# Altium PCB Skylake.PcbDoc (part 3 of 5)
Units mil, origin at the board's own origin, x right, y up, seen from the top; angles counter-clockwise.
Board outline 4000 x 4000 mil, 8 copper layers (TOP LAYER, GND1#2, SIG1#3, SIG2#4, GND2#5, SIG3#6, GND3#7, BOTTOM LAYER), stack 132.6 mil thick; 343 components, 142 nets, 972 pads, 752 vias.
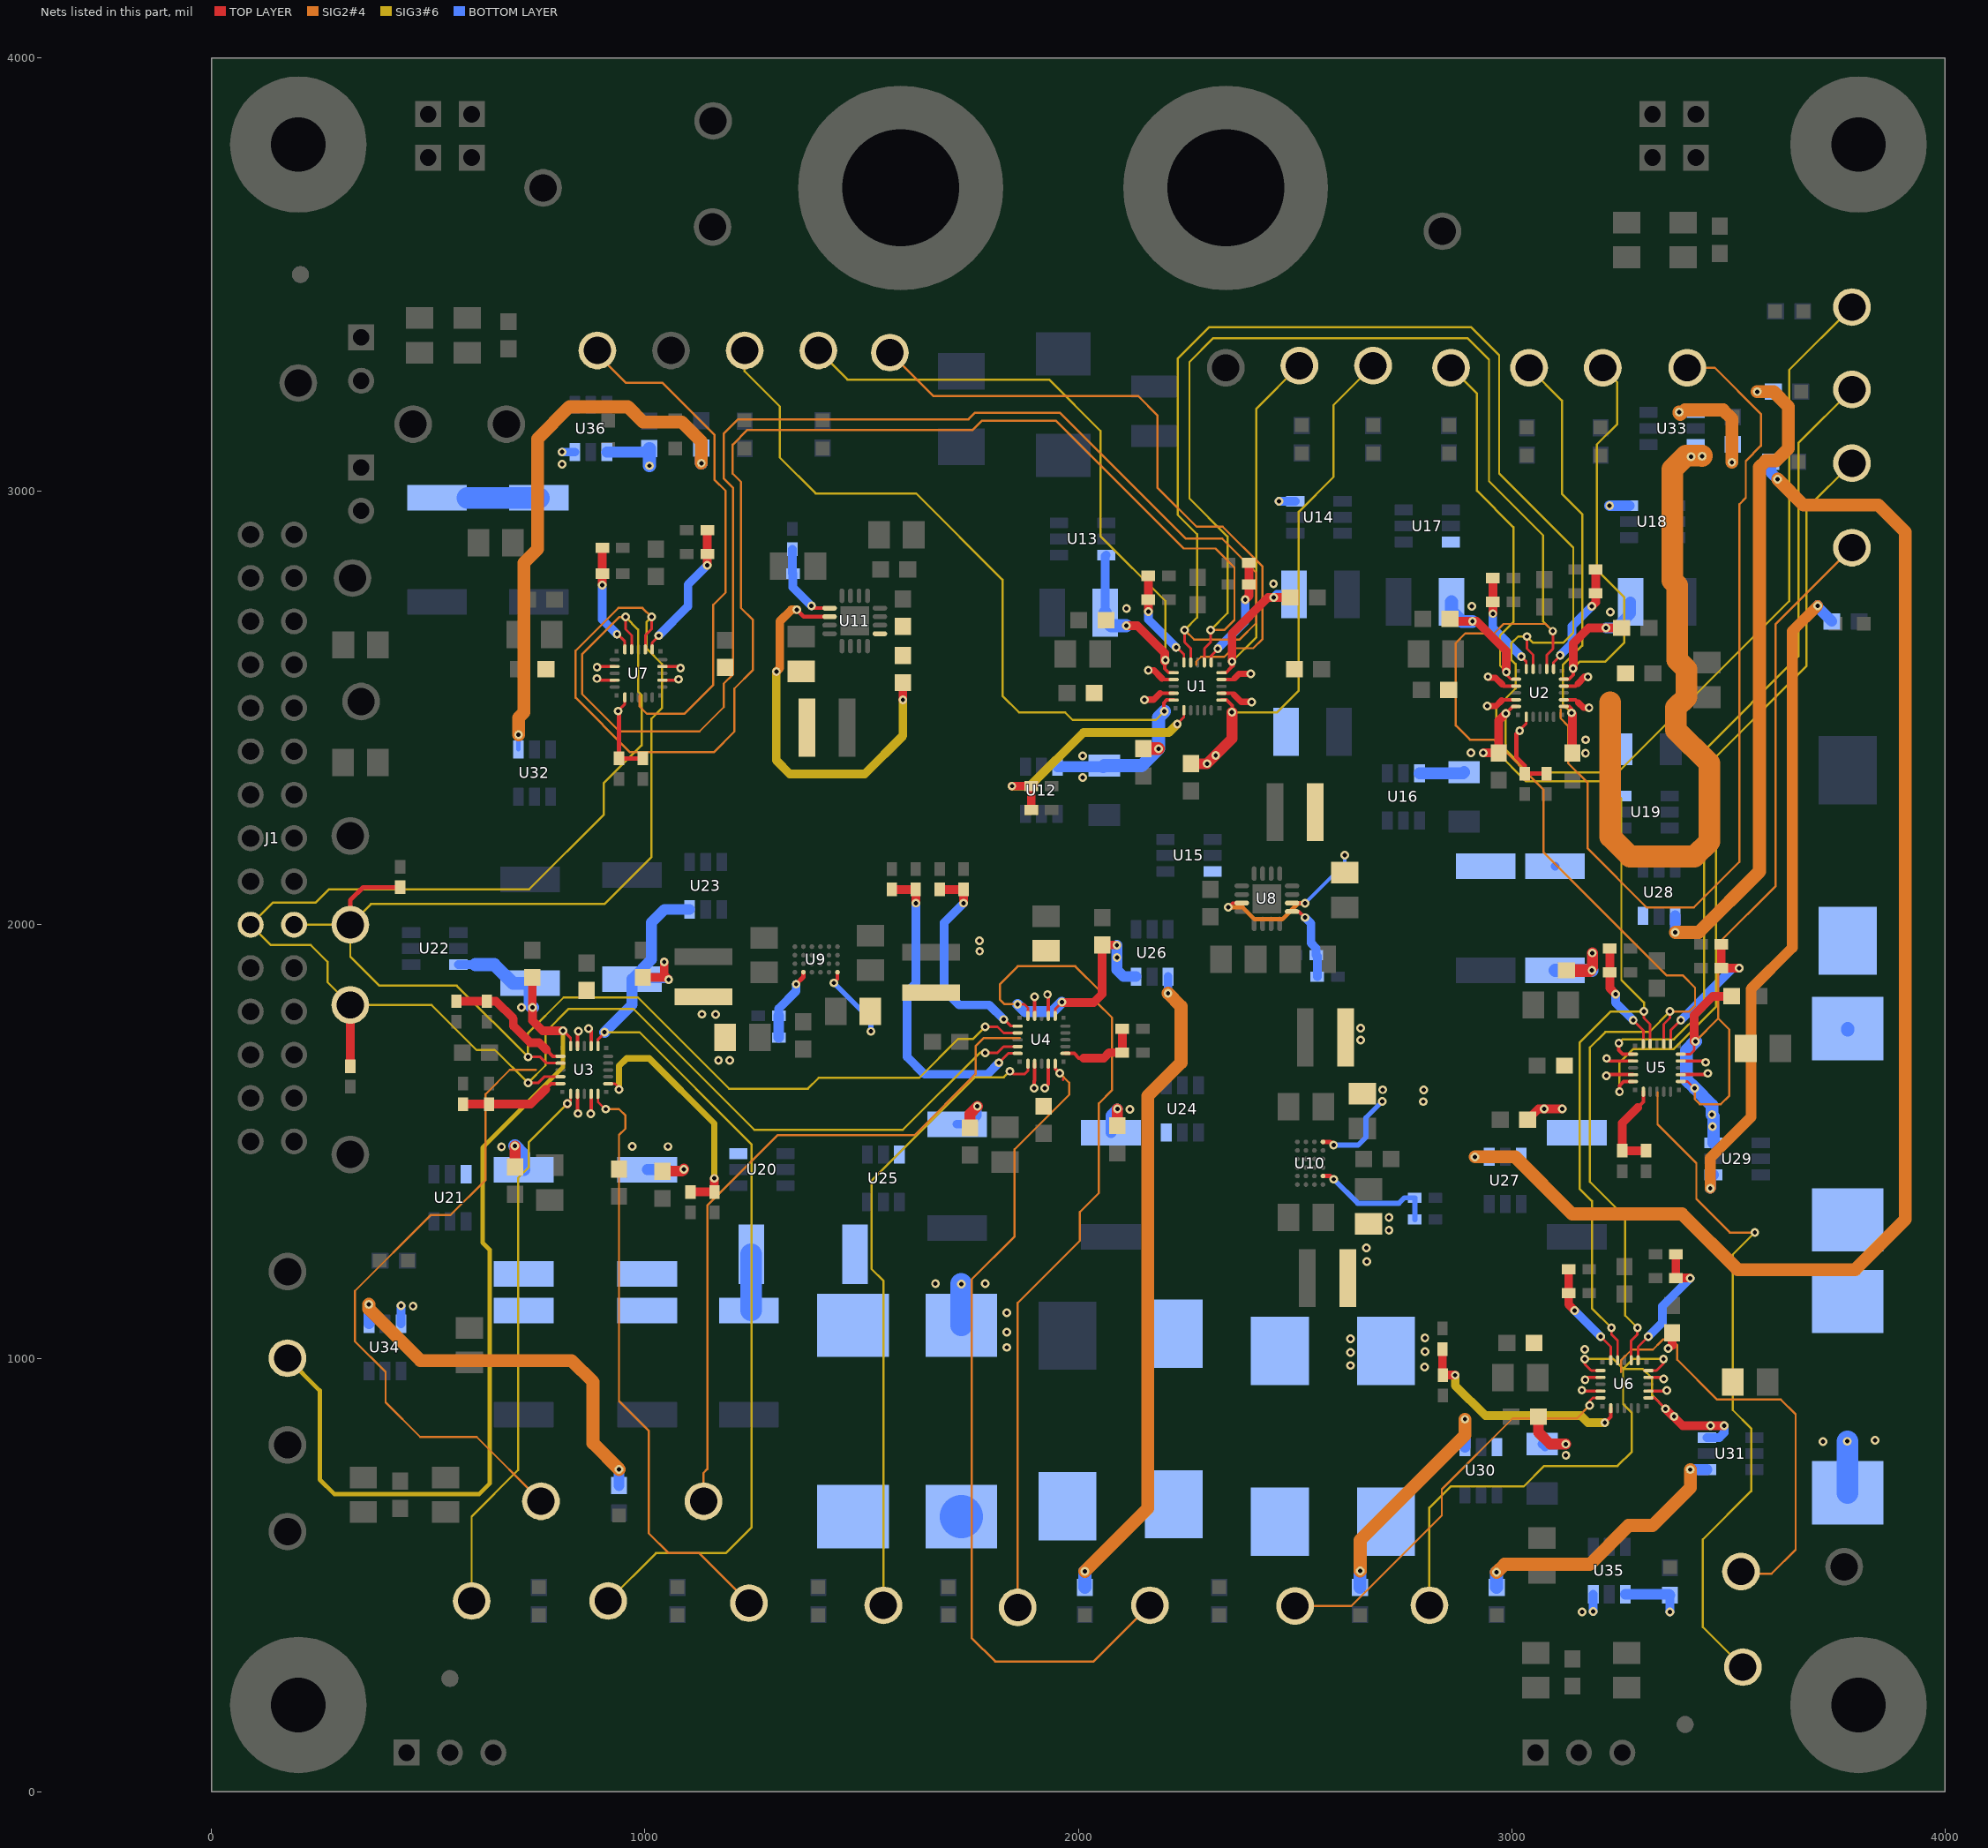
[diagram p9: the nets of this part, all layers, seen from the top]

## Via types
v1: diameter 20, hole 10, TOP LAYER to BOTTOM LAYER, 742 vias
v2: diameter 19.68, hole 7.87, TOP LAYER to BOTTOM LAYER, 10 vias

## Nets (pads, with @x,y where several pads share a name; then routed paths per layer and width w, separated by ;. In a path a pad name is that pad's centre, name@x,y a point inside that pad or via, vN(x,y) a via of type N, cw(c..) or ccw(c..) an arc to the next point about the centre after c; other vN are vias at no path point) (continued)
NetR17_2: R17.2 U26.1 | length 1513.1
  SIG2#4 w30: v1(2015.14,508.53) 2160,653.39 2160,1605 2236.74,1681.74 2236.74,1812.15 v1(2206.84,1842.05)
  BOTTOM LAYER w20: v1(2206.84,1842.05) 2207,1842.21 U26.1@2207,1880.5
  BOTTOM LAYER w30: R17.2@2015,471.5 v1@2015,508.39
NetR18_2: R18.2 U27.1 | length 3159.7
  SIG2#4 w30: v1(2915.19,1464.5) 3007.52,1464.5 3139.32,1332.7 3393.16,1332.7 3521.68,1204.18 3792.25,1204.18 3908.14,1320.07 3908.14,2906.31 3846.16,2968.29 3673.18,2968.29 v1(3613.56,3027.91)
  BOTTOM LAYER w25: v1(2915.19,1464.5) U27.1@2948,1464.5 ; R18.2@3597.27,3068.13 3597.27,3044.2 v1(3613.56,3027.91)
NetR19_2: R19.2 U28.1 | length 1528.1
  SIG2#4 w30: v1(3377.38,1982.27) 3430.89,1982.27 3571.55,2122.93 3571.55,3056.11 3585.93,3070.49 3609.85,3070.49 3638.31,3098.95 3638.31,3195.65 3604.11,3229.85 v1(3566.55,3229.85)
  BOTTOM LAYER w10: v1(3566.55,3229.85) 3566.7,3230 R19.2@3603.5,3230
  BOTTOM LAYER w25: U28.1@3377,2020.5 3377,1982.65 v1(3377.38,1982.27)
NetR20_2: R20.2 U29.1 | length 1530.3
  SIG2#4 w25: v1(3458,1392) 3458,1462.29 3552,1556.29 3552,1851.89 3647.48,1947.37 3647.48,2677.48 v1(3706,2736)
  BOTTOM LAYER w25: v1(3458,1392) 3458,1415.5 U29.1@3465.5,1423 ; v1(3706,2736) 3706,2732.5 R20.2@3738.5,2700
NetR21_2: R21.2 U30.1 | length 551.6
  SIG2#4 w30: v1(2650.14,509.51) 2650.14,580.37 2892.11,822.34 v1(2892.11,859.17)
  BOTTOM LAYER w25: U30.1@2892,795.19 v1@2892,859.06
  BOTTOM LAYER w30: R21.2@2650,471.5 v1@2650,509.37
NetR22_2: R22.2 U31.1 | length 642.6
  SIG2#4 w30: v1(2965,506.26) 2983.22,524.48 3179.76,524.48 3269.28,614 3324.46,614 3412,701.54 v1(3412,743)
  BOTTOM LAYER w25: v1(3412,743) U31.1@3450.5,743
  BOTTOM LAYER w30: R22.2@2965,471.5 v1(2965,506.26)
NetR23_2: R23.2 U32.1 | length 1271.5
  SIG2#4 w30: v1(708.2,2438.34) 708.2,2443.27 708.32,2443.39 708.32,2477.9 720.38,2489.96 720.38,2835.06 752.05,2866.73 752.05,3121.18 825.87,3195 960.38,3195 995.38,3160 1085,3160 1130,3115 v1(1130,3065)
  BOTTOM LAYER w10: U32.1@708,2404.5 708,2443.07 708.2,2443.27 v1(708.2,2438.34)
  BOTTOM LAYER w30: v1(1130,3065) R23.2@1130,3100
NetR24_2: R24.2 U33.1 | length 320.7
  SIG2#4 w30: v1(3386,3183) 3386,3180 3389,3177 3399.59,3187.59 3487.99,3187.59 3508,3167.58 v1(3508,3067)
  BOTTOM LAYER w20: v1(3386,3183) 3423.5,3183 U33.1@3424.5,3182 ; v1(3508,3067) 3508,3106.5 R24.2@3510,3108.5
NetR25_2: R25.2 U34.1 | length 906
  SIG2#4 w30: v1(362.91,1124.29) 362.91,1113.68 482.11,994.49 830.65,994.49 880,945.14 880,803.67 v1(940.14,743.53)
  BOTTOM LAYER w10: v1(362.91,1124.29) v1@363,1124.2 ; v1@940,743.39 v1(940.14,743.53)
  BOTTOM LAYER w25: U34.1@363,1079.5 v1@363,1124.2 ; R25.2@940,706.5 v1@940,743.39
NetR26_2: R26.2 U35.1 | length 142.3
  BOTTOM LAYER w20: v1(3365,415) R26.2@3365,453.5
  BOTTOM LAYER w25: U35.1@3262,455.5 3363,455.5 R26.2@3365,453.5
NetR27_2: R27.2 U36.1 | length 140.8
  BOTTOM LAYER w25: U36.1@912,3090.5 1002,3090.5 R27.2@1010,3098.5
  BOTTOM LAYER w30: v1(1010,3059) R27.2@1010,3098.5
NetR29_1: R29.1 R32.2 U1.6 | length 578.8
  TOP LAYER w6: v1(2228.21,2462.92) 2228.21,2464.16 2243.5,2479.45 U1.6@2243.5,2494.88
  TOP LAYER w20: v1(1846.68,2319.94) 1846.74,2320 R29.1@1891.38,2320 R32.2@1891.38,2265
  SIG3#6 w20: v1(1846.68,2319.94) 1887.94,2319.94 2011.58,2443.58 2208.87,2443.58 v1(2228.21,2462.92)
NetR30_1: R30.1 R33.2 U1.16 | length 266
  TOP LAYER w6: U1.16@2306.5,2605.12 2306.5,2620.55 2321.79,2635.84 v1(2321.79,2637.08)
  TOP LAYER w20: v1(2385,2750) 2393.62,2758.62 R30.1@2393.62,2785 R33.2@2393.62,2835
  BOTTOM LAYER w20: v1(2321.79,2637.08) 2385,2700.29 v1(2385,2750)
NetR31_1: R31.1 R34.2 U1.20 | length 236.8
  TOP LAYER w6: v1(2225.38,2640.26) 2225.38,2641.83 2243.5,2623.71 U1.20@2243.5,2605.12
  TOP LAYER w20: v1@2161.38,2722.82 R31.1@2161.38,2750 R34.2@2161.38,2805
  BOTTOM LAYER w20: v1(2161.56,2722.64) 2161.56,2704.08 v1(2225.38,2640.26)
NetR39_1: R39.1 R42.2 U2.6 | length 198.6
  TOP LAYER w6: v1(3018.21,2447.92) 3018.21,2449.16 3033.5,2464.45 U2.6@3033.5,2479.88
  TOP LAYER w10: v1(3018.21,2447.92) 3010.85,2440.56 3010.85,2386.06 3030,2366.91 R39.1@3030,2348.62 R42.2@3080,2348.62
NetR40_1: R40.1 R43.2 U2.16 | length 270.1
  TOP LAYER w6: U2.16@3096.5,2590.12 3096.5,2605.55 3111.79,2620.84 v1(3111.79,2622.08)
  TOP LAYER w20: v1(3185,2735) 3193.62,2743.62 R40.1@3193.62,2765 R43.2@3193.62,2820
  BOTTOM LAYER w20: v1(3111.79,2622.08) 3139.07,2649.36 3139.07,2689.07 v1(3185,2735)
NetR41_1: R41.1 R44.2 U2.20 | length 241.9
  TOP LAYER w6: v1(3022.2,2618.44) 3033.5,2607.14 U2.20@3033.5,2590.12
  TOP LAYER w20: v1(2956.31,2717.85) 2956.38,2717.92 R41.1@2956.38,2745 R44.2@2956.38,2800
  BOTTOM LAYER w20: v1(2956.31,2717.85) 2956.31,2684.33 v1(3022.2,2618.44)
NetR50_1: R50.1 R53.2 U3.6 | length 602.9
  TOP LAYER w6: U3.6@915.12,1633.5 930.55,1633.5 v1@944.05,1620 ; v1(940,1620) v1@944.05,1620 ; v1@944.05,1620 945.29,1620 947.08,1618.21 945.84,1618.21 v1@944.05,1620
  TOP LAYER w20: R50.1@1105,1383.62 R53.2@1160,1383.62 v1(1160,1415)
  SIG3#6 w15: v1(940,1620) 940,1674.31 957.59,1691.9 1009.62,1691.9 1160,1541.52 v1(1160,1415)
NetR51_1: R51.1 R54.2 U3.16 | length 302.4
  TOP LAYER w8: 772.6,1711.54 787.64,1696.5 U3.16@804.88,1696.5
  TOP LAYER w20: R54.2@565,1823.62 R51.1@635,1823.62 656.26,1823.62 696.31,1783.57 696.31,1766.78 734.97,1728.12 756.02,1728.12 772.6,1711.54
NetR52_1: R52.1 R55.2 U3.20 | length 244.4
  TOP LAYER w8: 770.7,1620.6 783.6,1633.5 U3.20@804.88,1633.5
  TOP LAYER w20: R55.2@580,1586.38 R52.1@640,1586.38 736.48,1586.38 770.7,1620.6
NetR56_2: R56.2 R57.1
NetR58_2: R58.2 R59.1
NetR62_1: R62.1 R65.2 U4.6 | length 195.8
  TOP LAYER w8: U4.6@1970.12,1703.19 1990.45,1703.19 2001.06,1692.58 2012.18,1692.58
  TOP LAYER w20: 2012.18,1692.58 2058.89,1692.58 2071.31,1705 R62.1@2101.38,1705 R65.2@2101.38,1760
NetR63_1: R63.1 R66.2 U4.16 | length 509.9
  TOP LAYER w6: v1(1827.92,1781.48) 1829.16,1781.48 1844.45,1766.18 U4.16@1859.88,1766.18
  TOP LAYER w20: R63.1@1680,2081.38 R66.2@1735,2081.38 v1(1735,2050)
  BOTTOM LAYER w20: v1(1735,2050) 1690,2005 1690,1849.49 1724.49,1815 1794.4,1815 v1(1827.92,1781.48)
NetR64_1: R64.1 R67.2 U4.20 | length 741.1
  TOP LAYER w6: v1(1816.47,1681.58) 1838.08,1703.19 U4.20@1859.88,1703.19
  TOP LAYER w20: R67.2@1570,2081.38 R64.1@1625,2081.38 v1(1625,2050)
  BOTTOM LAYER w20: v1(1625,2050) 1625,1865 1605,1845 1605,1695 1645,1655 1789.89,1655 v1(1816.47,1681.58)
NetR70_2: R70.2 R71.1 | length 0
NetR71_2: R71.2 R72.1
NetR72_2: R72.2 R73.1 | length 129.9
  BOTTOM LAYER w50: R73.1@1244.92,1110.08 R72.2@1244.92,1240
NetR75_1: R75.1 R78.2 U5.6 | length 211.4
  TOP LAYER w8: 3290.78,1578.39 3303.5,1591.11 U5.6@3303.5,1614.88
  TOP LAYER w20: 3290.78,1578.39 3255,1542.61 R75.1@3255,1478.62 R78.2@3310,1478.62
NetR76_1: R76.1 R79.2 U5.16 | length 345.7
  TOP LAYER w6: U5.16@3366.5,1725.12 3366.5,1756.5 v1(3390,1780)
  TOP LAYER w20: R79.2@3483.62,1955 R76.1@3483.62,1900 v1(3525,1900)
  BOTTOM LAYER w20: v1(3390,1780) 3510,1900 v1(3525,1900)
NetR77_1: R77.1 R80.2 U5.20 | length 251.8
  TOP LAYER w6: v1(3280,1780) 3303.5,1756.5 U5.20@3303.5,1725.12
  TOP LAYER w20: R80.2@3226.38,1945 R77.1@3226.38,1890 3226.38,1853.62 v1(3240,1840)
  BOTTOM LAYER w20: v1(3240,1840) 3240,1820 v1(3280,1780)
NetR82_2: R82.2 R83.1 | length 0
NetR84_2: R84.2 R85.1
NetR85_2: R85.2 R86.1 | length 3.5
  BOTTOM LAYER w30: R85.2@3775,1756.94 R85.2@3775,1760.47
NetR87_1: R87.1 R90.2 U6.6 | length 533.2
  TOP LAYER w8: v1(3214.73,851.2) 3228.5,864.97 U6.6@3228.5,884.88
  TOP LAYER w20: R90.2@2840,1021.38 2840,962.07 R87.1@2840.9,961.17 2869.26,961.17 v1(2869.53,960.9)
  SIG3#6 w20: v1(2869.53,960.9) 2869.53,937.2 2939.21,867.52 3159.12,867.52 3175.44,851.2 v1(3214.73,851.2)
NetR88_1: R88.1 R91.2 U6.16 | length 326.3
  TOP LAYER w6: U6.16@3291.5,995.12 3291.5,1026.5 v1(3315,1050)
  TOP LAYER w20: R91.2@3378.62,1240 R88.1@3378.62,1185 v1@3410.93,1185
  BOTTOM LAYER w20: v1(3315,1050) 3347.39,1082.39 3347.39,1120.28 v1(3411.52,1184.41)
NetR89_1: R89.1 R92.2 U6.20 | length 250.1
  TOP LAYER w6: v1(3205,1050) 3228.5,1026.5 U6.20@3228.5,995.12
  TOP LAYER w20: R92.2@3131.38,1205 R89.1@3131.38,1150 3131.38,1123.62 v1(3145,1110)
  BOTTOM LAYER w20: v1(3145,1110) v1(3205,1050)
NetR94_2: R94.2 R95.1
NetR95_2: R95.2 R96.1
NetR96_2: R96.2 R97.1
NetR99_1: R99.1 R102.2 U7.6 | length 203.3
  TOP LAYER w6: v1@938.21,2494.16 953.5,2509.45 U7.6@953.5,2524.88
  TOP LAYER w10: v1@938.21,2494.16 940,2492.37 R99.1@940,2383.62 R102.2@995,2383.62
  other v1: 938.21,2492.92
NetR100_1: R100.1 R103.2 U7.16 | length 327.5
  TOP LAYER w6: U7.16@1016.5,2635.12 1016.5,2650.55 1031.79,2665.84 v1(1031.79,2667.08)
  TOP LAYER w20: v1(1143.5,2829.3) 1143.62,2829.42 R100.1@1143.62,2855 R103.2@1143.62,2910
  BOTTOM LAYER w20: v1(1031.79,2667.08) 1099.12,2734.41 1099.12,2784.92 v1(1143.5,2829.3)
NetR101_1: R101.1 R104.2 U7.20 | length 259.5
  TOP LAYER w6: v1(935.38,2670.26) 935.38,2671.83 953.5,2653.71 U7.20@953.5,2635.12
  TOP LAYER w20: v1(901.43,2783.39) R101.1@901.38,2810 R104.2@901.38,2870
  BOTTOM LAYER w20: v1(901.43,2783.39) 901.43,2704.21 v1(935.38,2670.26)
NetR105_2: R105.2 R106.1 | length 165
  BOTTOM LAYER w50: 590,2985.08 R105.2@755,2985.08
NetR107_2: R107.2 R108.2 U8.13 | length 184
  TOP LAYER w8: U8.13@2493.07,2030.47 2509.03,2030.47 v1(2522.85,2016.65)
  BOTTOM LAYER w20: v1(2522.85,2016.65) 2536.92,2002.58 2536.92,1957.53 2548.62,1945.83 R107.2@2548.62,1930 2551.38,1927.24 R108.2@2551.38,1880
NetR109_1: R109.1 R110.2 U9.E4 | length 174
  TOP LAYER w10: v1(1348.77,1862.82) 1365.47,1879.52 U9.E4@1365.47,1890.47
  BOTTOM LAYER w20: R110.2@1308.62,1790 1308.62,1806.65 1348.77,1846.8 v1(1348.77,1862.82)
  BOTTOM LAYER w25: R109.1@1308.62,1740 R110.2@1308.62,1790
NetR111_1: R111.1 R112.2 U10.E4 | length 293.1
  TOP LAYER w10: U10.E4@2564.37,1420.31 2581.62,1420.31 v1(2589.13,1412.8)
  BOTTOM LAYER w12: v1(2589.13,1412.8) 2644.34,1357.59 2739.8,1357.59 2752.21,1370 R111.1@2776.38,1370 R112.2@2776.38,1320
NetR113_1: R113.1 R114.2 U11.13 | length 195.7
  TOP LAYER w8: v1(1384.18,2735.97) 1389.62,2730.53 U11.13@1428.88,2730.53
  BOTTOM LAYER w20: R114.2@1340,2866.38 1340,2811.38 R113.1@1341.38,2810 1341.38,2778.77 v1(1384.18,2735.97)
NetR115_1: R115.1 R116.2 U11.5
SCL: J1.20 R1.1 SCL.1 U1.17 U2.17 U3.17 U4.17 U5.17 U6.17 U7.17 | length 11517.1
  TOP LAYER w6: v1(730,1695) 758.41,1695 772.66,1680.75 U3.17@804.88,1680.75 ; U7.17@1000.75,2635.12 1000.75,2667.34 1015,2681.59 v1(1015,2710) ; v1(1785,1764.68) 1813.41,1764.68 1827.66,1750.43 U4.17@1859.88,1750.43 ; U1.17@2290.75,2605.12 2290.75,2637.34 2305,2651.59 v1(2305,2680) ; U2.17@3080.75,2590.12 3080.75,2622.34 3095,2636.59 3095,2677.03 v1(3094.7,2677.33) ; U6.17@3275.75,995.12 3275.75,1040.75 3290,1055 v1(3290,1070) ; U5.17@3350.75,1725.12 3350.75,1770.75 3365,1785 v1(3365,1800)
  TOP LAYER w10: SCL.1@320,2000 320,2056.94 349.44,2086.38 R1.1@435,2086.38
  SIG2#4 w5: v1(1015,2710) 994.19,2730.81 938.46,2730.81 840.12,2632.47 840.12,2523.77 965.74,2398.15 1158.47,2398.15 1206.27,2445.95 1206.27,2544.8 1249.36,2587.89 1249.36,2703.01 1221.38,2730.99 1221.38,3021.62 1202.35,3040.65 1202.35,3107.72 1236.28,3141.65 1756.18,3141.65 1777.72,3163.19 1947.96,3163.19 2243.03,2868.12 2316.68,2868.12 2360.13,2824.67 2360.13,2703.11 2337.02,2680 v1(2305,2680) ; v1(3094.7,2677.33) 3078.02,2694.01 2981.05,2694.01 2959.19,2672.15 2892.89,2672.15 2870.86,2650.12 2870.86,2459.71 2903.57,2427 2958.24,2427 3073,2312.24 3073,2167.49 3357.05,1883.44 3394.14,1883.44 3422.96,1854.62 3422.96,1813.64 3409.32,1800 v1(3365,1800)
  SIG3#6 w5: J1.20@190,2000 SCL.1@320,2000 ; v1(1015,2710) 1004,2699 1004,2636.88 1038.89,2601.99 1038.89,2499.65 1015,2475.76 1015,2156.41 906.25,2047.66 367.66,2047.66 SCL.1@320,2000 ; v1(1785,1764.68) 1757.32,1737 1723,1737 1633,1647 1401,1647 1376,1622 1194,1622 983.78,1832.22 812.12,1832.22 730,1750.11 v1(730,1695) 565.54,1859.46 387,1859.46 320,1926.46 SCL.1@320,2000 ; v1(2305,2680) 2344.04,2719.04 2344.04,2895.92 2256.32,2983.64 2256.32,3298.32 2311.4,3353.4 2897.67,3353.4 2947.49,3303.58 2947.49,3023.29 3072.15,2898.63 3072.15,2699.88 v1(3094.7,2677.33) ; v1(3290,1070) 3261.52,1098.48 3261.52,1325.76 3180.11,1407.17 3180.11,1716.82 3215.94,1752.65 3317.65,1752.65 v1(3365,1800)
SDA: J1.19 R2.1 SDA.1 U1.19 U2.19 U3.19 U4.19 U5.19 U6.19 U7.19 | length 11600.7
  TOP LAYER w6: v1(730,1635) 753.16,1635 767.41,1649.25 U3.19@804.88,1649.25 ; v1(955,2710) 955,2681.88 969.25,2667.63 U7.19@969.25,2635.12 ; v1(1785,1704.69) 1813.12,1704.69 1827.37,1718.94 U4.19@1859.88,1718.94 ; v1(2245,2680) 2245,2651.88 2259.25,2637.63 U1.19@2259.25,2605.12 ; v1(3035,2665) 3035,2636.88 3049.25,2622.63 U2.19@3049.25,2590.12 ; v1(3230,1070) 3230,1055 3244.25,1040.75 U6.19@3244.25,995.12 ; v1(3305,1800) 3305,1785 3319.25,1770.75 U5.19@3319.25,1725.12
  TOP LAYER w20: R2.1@320,1673.62 SDA.1@320,1815
  SIG2#4 w5: v1(955,2710) 940.85,2710 854.81,2623.96 854.81,2532.65 941.29,2446.17 1125.88,2446.17 1181.84,2502.12 1181.84,2556.51 1203.51,2578.18 1203.51,3007.8 1181.31,3030 1181.31,3132.55 1215,3166.24 1746.43,3166.24 1761.65,3181.46 1956.99,3181.46 2247.76,2890.69 2332.14,2890.69 2410.51,2812.32 2410.51,2696.5 2372.04,2658.03 2266.97,2658.03 v1(2245,2680)
  SIG3#6 w5: v1(955,2710) 984,2681 984,2538.29 992.15,2530.14 992.15,2413.87 904.5,2326.22 904.5,2253.5 732.83,2081.83 270.76,2081.83 239.93,2051 141,2051 J1.19@90,2000 137,1953 229,1953 267.5,1914.5 267.5,1867.5 SDA.1@320,1815 507.56,1815 611.41,1711.15 653.85,1711.15 v1(730,1635) 770.44,1675.44 770.44,1752.44 823.97,1805.97 973.03,1805.97 1252,1527 1595,1527 1772.69,1704.69 v1(1785,1704.69) ; v1(2245,2680) 2273.7,2708.7 2273.7,2901.3 2229,2946 2229,3305.55 2302.45,3379 2905.62,3379 2970.92,3313.7 2970.92,3041.35 3142,2870.27 3142,2674 3118.34,2650.34 3049.66,2650.34 v1(3035,2665) 3014.68,2665 2998.8,2649.12 2998.8,2611.76 3008.96,2601.6 3008.96,2544.96 2964.2,2500.2 2964.2,2399.91 3033.33,2330.78 3213.44,2330.78 3252.97,2291.25 3252.97,1872.82 3305,1820.79 v1(3305,1800) 3228.37,1800 3156.58,1728.21 3156.58,1391.17 3184.95,1362.8 3184.95,1115.05 v1(3230,1070)
V1(1.8V): C24.1 C27.1 C30.1 C37.1 C40.1 L1.2 U1.2 U1.4 U1.12 U1.14 U1_V1(1.8V).1 U2.2 U2.4 U2.12 U2.14 U2_V1(1.8V).1 U8.7 U8.14 U33.3 | length 6131.9
  TOP LAYER w8: 2188.91,2534.25 U1.4@2219.88,2534.25 ; 2192.68,2568.61 2195.54,2565.75 U1.2@2219.88,2565.75 ; U1.12@2330.12,2534.25 2355.19,2534.25 2359.15,2530.29 ; U1.14@2330.12,2565.75 2357.39,2565.75 2360.44,2568.8 ; v1(2345.74,2040.25) 2355.65,2050.16 U8.7@2376.93,2050.16 ; U8.14@2493.07,2050.16 2523.12,2050.16 v1(2523.33,2049.95) ; 2976.44,2517.12 2978.57,2519.25 U2.4@3009.88,2519.25 ; 2977.4,2554.88 2981.53,2550.75 U2.2@3009.88,2550.75 ; U2.12@3120.12,2519.25 3146.78,2519.25 3153.97,2512.06 ; U2.14@3120.12,2550.75 3146.67,2550.75 3152.35,2556.43
  TOP LAYER w15: v1(2152.42,2519.14) 2173.8,2519.14 2188.91,2534.25 ; v1(2161.2,2587.22) 2174.07,2587.22 2192.68,2568.61 ; 2359.15,2530.29 2375.27,2514.17 2399.58,2514.17 v1(2399.94,2513.81) ; 2360.44,2568.8 2370.59,2578.95 2397.37,2578.95 v1(2397.66,2579.24) ; v1(2943.74,2504.56) 2963.88,2504.56 2976.44,2517.12 ; v1(2945,2572.33) 2947.45,2569.88 2962.4,2569.88 2977.4,2554.88 ; 3152.35,2556.43 3167.99,2572.07 v1(3175.93,2572.07) ; 3153.97,2512.06 3165.54,2500.49 v1(3178.22,2500.49)
  SIG2#4 w5: 1565,3320 1665,3220 2137.71,3220 2182.25,3175.46 2182.25,3008.89 2273.05,2918.09 2333.14,2918.09 2425.02,2826.21 2425.02,2659.61 2403.45,2638.04 2356.47,2638.04 2336.71,2618.28 2283.14,2618.28 2272.16,2607.3 2272.16,2599.4 ; 3112.96,2495.99 3112.96,2476.3 3130.07,2459.19 3130.07,2372.76 3175.39,2327.44 3175.39,2175.94 3311.33,2040 3420,2040 3525.16,2145.16 3525.16,2970.16 3540,2985 3540,3070 3575,3105 3575,3178.62 3468.62,3285 3405,3285
  SIG2#4 w10: v1(2345.74,2040.25) 2379.14,2040.25 2406.68,2012.71 2470.46,2012.71 2507.7,2049.95 v1(2523.33,2049.95)
  SIG2#4 w50: 3226.56,2513.75 3226.7,2513.61 3226.7,2203.39 3272.54,2157.55 3421.48,2157.55 3455.86,2191.93 3455.86,2372.56 3379.02,2449.4 3379.02,2500.62 3402.85,2524.45 3402.85,2590.03 3381.72,2611.16 3381.72,2783.03 3370.68,2794.07 3370.68,3050.95 3401.7,3081.97 3414.04,3081.97 3438.77,3081.97 3438.94,3082.14 3439,3082.08 v1(3439,3081)
  BOTTOM LAYER w8: v1(2523.33,2049.95) 2614.35,2140.97 v1(2614.35,2160.78)
  other v1: 3414,3080
V1.8DX_3G4G: "V1.8Dx_3G4G [1.8V,0.07A].1" C43.2 R46.1 U2.1 U17.3 | length 1097.5
  TOP LAYER w6: v1@2987.18,2587.95 2987.18,2577.57 2998.25,2566.5 U2.1@3009.88,2566.5
  TOP LAYER w20: C43.2@2861.5,2700 2909.14,2700 v1(2909.29,2699.85) 2918.98,2699.85 2987.18,2631.65 v1@2987.18,2587.95
  SIG3#6 w5: 2860,3285 2919.93,3225.07 2919.93,3001.23 3003.81,2917.35 3003.81,2698.33 2972.93,2667.45 2972.93,2597.75 v1(2987.61,2583.07)
  BOTTOM LAYER w25: R46.1@2859.5,2746.52 R46.1@2861.02,2745
  BOTTOM LAYER w30: R46.1@2861.02,2745 2861.02,2723.47 2884.64,2699.85 v1(2909.29,2699.85)
  other v1: 2907.65,2734.49
V1.8DX_AUDIO: "V1.8Dx_AUDIO [1.8V,0.13A].1" C34.2 R37.1 U1.15 U14.3 | length 1115.7
  TOP LAYER w8: U1.15@2330.12,2581.5 2340.86,2581.5 2353.22,2593.85 ; v1(2354.51,2607.16) 2353.22,2605.86 2353.22,2593.85 ; v1@2356.99,2597.63 2353.22,2593.85
  TOP LAYER w20: v1(2354.51,2607.16) 2354.51,2672 2437.68,2755.17 v1(2450.71,2755.17) 2450.88,2755 C34.2@2488.5,2755
  SIG3#6 w5: v1(2354.51,2607.16) 2410.84,2663.49 2410.84,3190.84 2510,3290
  BOTTOM LAYER w20: v1(2450.71,2755.17) 2457.74,2762.2 R37.1@2497.98,2762.2 ; v1(2463.03,2976.91) 2463.12,2977 U14.3@2500.5,2977
  other v1: 2450.28,2786.99
V1.8DX_SENSORS: "V1.8Dx_SENSORS [1.8V,0.07A].1" C33.2 R36.1 U1.1 U13.3 | length 1699.8
  TOP LAYER w8: v1@2199.13,2607.32 2199.13,2590.77 2208.4,2581.5 U1.1@2219.88,2581.5
  TOP LAYER w20: v1@2110.09,2690 2110.44,2689.65 v1(2110.44,2689.9) 2135.83,2689.9 2199.13,2626.6 v1@2199.13,2607.32
  SIG3#6 w5: 1400,3325 1467.12,3257.88 1932.55,3257.88 2051.01,3139.42 2051.01,2896.78 2200.73,2747.06 v1(2200.73,2610.24)
  BOTTOM LAYER w20: R36.1@2062.05,2720 2062.05,2850.55 U13.3@2064.5,2853
  BOTTOM LAYER w30: R36.1@2062.05,2720 2062.05,2703.25 2075.4,2689.9 v1(2110.44,2689.9)
  other v1: 2111.05,2729.66
V1.8DX_SSD: "V1.8Dx_SSD [1.8V,0.07A].1" C35.2 R38.1 U1.11 U15.3 | length 1221.2
  TOP LAYER w8: U1.11@2330.12,2518.5 2342.21,2518.5 2355.31,2505.4 2355.31,2491.24 v1(2354.39,2490.32)
  TOP LAYER w25: C35.2@2260,2371.5 2296.6,2371.5 v1(2296.83,2371.73) 2354.39,2429.29 v1(2354.39,2490.32)
  SIG3#6 w5: v1(2354.39,2490.32) 2458.82,2490.32 2508.48,2539.98 2508.48,2952.96 2588.69,3033.17 2588.69,3198.69 2680,3290
  other v1: 2316.77,2390.59
V1.8DX_USBSDIO: "V1.8Dx_USBSDIO [1.8V,0.05A].1" C42.2 R45.1 U2.5 U16.3 | length 1928.3
  TOP LAYER w8: v1(2986.1,2487.13) 3002.47,2503.5 U2.5@3009.88,2503.5
  TOP LAYER w20: v1(2934.52,2396.37) 2934.65,2396.5 C42.2@2970,2396.5 2970,2471.03 v1(2986.1,2487.13)
  SIG3#6 w5: v1(2986.1,2487.13) 2986.1,2403.56 3037.83,2351.83 3245.2,2351.83 3640.22,2746.85 3640.22,3280.22 3785,3425
  BOTTOM LAYER w28: U16.3@2787,2349.5 2887.41,2349.5 R45.1@2890,2352.09
  other v1: 2906.07,2396.88
V1.8DX_WIFI: "V1.8Dx_WIFI [1.8V,0.07A].1" C44.2 R47.1 U2.15 U18.3 | length 1203.8
  TOP LAYER w8: U2.15@3120.12,2566.5 3132.22,2566.5 3142.2,2576.48 v1@3142.2,2590.4
  TOP LAYER w20: v1(3141.4,2591.2) 3142.2,2592 3142.2,2649.27 3177.64,2684.71 v1(3217.08,2684.71) 3217.37,2685 C44.2@3253.5,2685
  SIG3#6 w5: v1(3141.4,2591.2) 3157.59,2607.39 3216.31,2607.39 3259.29,2650.37 3259.29,2756.03 3196.09,2819.23 3196.09,3107.94 3243.61,3155.46 3243.61,3251.39 3210,3285
  BOTTOM LAYER w25: v1(3217.08,2684.71) 3240.43,2684.71 3273.98,2718.26 R47.1@3273.98,2745 ; v1@3225.74,2966.86 3225.88,2967 U18.3@3270.5,2967
  other v1: 3227.47,2721.76 3225.77,2967.11
V1.8M: "V1.8M [1.8V,0.01A].1" C45.2 R48.1 U2.11 U19.3 | length 1005.2
  TOP LAYER w8: U2.11@3120.12,2503.5 3133.36,2503.5 3137.9,2498.96 v1(3137.9,2488.83)
  TOP LAYER w20: v1(3137.9,2488.83) 3140,2486.73 C45.2@3140,2396.5 C45.2@3145.93,2402.43
  SIG3#6 w5: 3040,3285 3115.62,3209.38 3115.62,2994.35 3162.47,2947.5 3162.47,2643.84 3117.71,2599.08 3117.71,2509.02 v1(3137.9,2488.83)
  other v1: 3170.05,2395.64 3170.44,2426.81
V1.8S: "V1.8S [1.8V,0.10A].1" C32.2 R35.1 U1.5 U12.3 | length 2006.1
  TOP LAYER w8: v1@2197.23,2492.4 2197.23,2512.1 2203.63,2518.5 U1.5@2219.88,2518.5
  TOP LAYER w20: v1@2184.7,2406.5 v1(2184.99,2406.21)
  TOP LAYER w30: C32.2@2150,2406.5 v1@2184.7,2406.5
  SIG3#6 w5: 1230,3325 1230,3276.88 1311,3195.88 1311,3078.12 1393.83,2995.29 1625.71,2995.29 1824.85,2796.15 1824.85,2528.19 1863.04,2490 1969.32,2490 1986.63,2472.69 2178.87,2472.69 v1(2198.58,2492.4)
  BOTTOM LAYER w25: U12.3@1952,2364.5 R35.1@2057.41,2364.5
  BOTTOM LAYER w30: R35.1@2057.41,2364.5 R35.1@2060,2367.09 2145.87,2367.09 v1(2184.99,2406.21) 2184.99,2478.81 v1(2198.58,2492.4)
  other v1: 2009.96,2339.47 2009.96,2389.58
V2(3.3V): C49.1 C50.1 C53.1 C56.1 C63.1 C66.1 L2.2 L3.2 U3.2 U3.4 U3.12 U3.14 U3_V2(3.3V).1 U4.2 U4.4 U4.12 U4.14 U4_V2(3.3V).1 U9.A4 U34.3 | length 3689
  TOP LAYER w8: U3.2@844.25,1609.88 844.25,1565.4 v1(845.06,1564.59) ; U3.14@844.25,1720.12 844.25,1752.13 v1(846.6,1754.48) ; v1(869.41,1760.44) 875.75,1754.1 U3.12@875.75,1720.12 ; v1(874.55,1564.29) 874.55,1563.97 875.75,1565.17 U3.4@875.75,1609.88 ; v1(1435.65,1865.89) 1444.21,1874.45 U9.A4@1444.21,1890.47 ; v1(1898.1,1623.3) 1898.1,1639.1 1899.25,1640.25 U4.2@1899.25,1679.57 ; v1(1898.72,1834.12) 1899.25,1833.59 U4.14@1899.25,1789.8 ; v1(1922.11,1623.3) 1930.75,1631.93 U4.4@1930.75,1679.57 ; v1(1928.88,1839.3) 1930.75,1837.43 U4.12@1930.75,1789.8
  SIG2#4 w5: 747.91,1665.29 688.13,1665.29 632.19,1609.35 632.19,1411.6 550.62,1330.03 505.39,1330.03 330.66,1155.3 330.66,1039.11 401.44,968.33 401.44,898.1 481.24,818.3 611.7,818.3 760,670 ; 1135,670 1135,735.29 1143.91,744.2 1143.91,1352.54 1305.7,1514.33 1621.61,1514.33 1762.82,1655.54 1762.82,1720.15 1781.59,1738.92 1865.16,1738.92
  SIG2#4 w8: v1(1898.1,1623.3) v1@1898.46,1622.94
  BOTTOM LAYER w12: v1(1435.65,1865.89) 1521.36,1780.18 v1(1521.36,1754.05)
  BOTTOM LAYER w20: v1(436.9,1121.22) 437,1121.12 U34.3@437,1079.5
  other v1: 464.93,1120.09 1169.56,1687.18 1195.29,1686.95 1162.6,1793.39 1131.23,1793.62
V3(3.3V): C75.1 C76.1 C79.1 C82.1 C89.1 C92.1 L4.2 L5.2 U5.2 U5.4 U5.12 U5.14 U5_V3(3.3V).1 U6.2 U6.4 U6.12 U6.14 U6_V3(3.3V).1 U10.A4 U35.3 | length 3239.4
  TOP LAYER w8: v1(3161.74,926.23) 3163.72,924.25 U6.4@3204.88,924.25 ; v1(3169.03,950.23) 3174.55,955.75 U6.2@3204.88,955.75 ; v1(3218.43,1651.53) 3221.15,1654.25 U5.4@3279.88,1654.25 ; v1(3218.83,1691.72) 3224.8,1685.75 U5.2@3279.88,1685.75 ; U6.12@3315.12,924.25 3356.28,924.25 v1(3357.73,925.7) ; U6.14@3315.12,955.75 3347.14,955.75 v1(3350.83,952.06) ; U5.12@3390.12,1654.25 3449.53,1654.25 v1(3452.51,1657.23) ; U5.14@3390.12,1685.75 3443.85,1685.75 v1(3447.05,1682.55)
  TOP LAYER w10: U10.A4@2564.37,1499.06 2581.24,1499.06 v1(2588.77,1491.53)
  SIG2#4 w5: 3251.95,968.3 3252.29,968.64 3252.29,995.23 3276.93,1019.87 3325.71,1019.87 3344.7,1038.86 3348.92,1043.13 3368.81,1043.13 3382.08,1029.85 3382.08,996.4 3473.99,904.49 3620.94,904.49 3655,870.43 3655,558.35 3599.28,502.63 3534.24,502.63 3529.03,507.84 ; 3336.37,1613.91 3336.37,1539.45 3426,1449.82 3426,1367.17 3503.17,1290 v1(3560.91,1290)
  SIG3#6 w5: 3533.28,287.38 3440.7,379.96 3440.7,581.73 3552.38,693.41 3552.38,838.07 3510,880.45 3510,1239.09 v1(3560.91,1290)
  BOTTOM LAYER w12: v1(2588.77,1491.53) 2645.21,1491.53 2663.4,1509.72 2663.4,1554.8 v1(2701.24,1592.64)
  BOTTOM LAYER w20: U35.3@3188,455.5 3188,415.68 v1(3188.04,415.64)
  other v1: 3162.18,414.4 2665.5,1222.71 2664.61,1254.61 2716.79,1295.58 2716.79,1325.09 2795.94,1592.05 2701.99,1619.4 2796.7,1618.73 2651.04,1733.72 2651.44,1761.51
V3.3A_EC: "V3.3A_EC [3.3V,0.10A].1" C60.2 R60.1 U3.15 U22.3 | length 2319.4
  TOP LAYER w6: v1@810.38,1756.83 828.5,1738.71 U3.15@828.5,1720.12
  TOP LAYER w20: C60.2@740,1878.5 740,1809.91 v1(740.37,1809.54) 740.37,1778.82 763.93,1755.26 v1(810.38,1755.26)
  SIG3#6 w10: 175,1000 249.52,925.48 249.52,720.03 282.79,686.76 617.5,686.76 641.47,710.73 641.47,1250.44 625.07,1266.84 625.07,1485.57 810.38,1670.88 v1(810.38,1755.26)
  BOTTOM LAYER w20: U22.3@569.5,1908 608.69,1908
  BOTTOM LAYER w30: 608.69,1908 652.57,1908 695.65,1864.92 R60.1@735,1864.92 735,1814.91 v1(740.37,1809.54)
  other v1: 715.1,1809.66
V3.3DX_3G4G: "V3.3Dx_3G4G [3.3V,2.4A].1" C70.2 R70.1 U4.11 U4.15 U26.3 | length 2617.6
  TOP LAYER w6: v1(1859.82,1816.55) 1875.35,1816.55 1883.5,1808.39 U4.15@1883.5,1789.8 ; U4.11@1946.5,1789.8 1946.5,1805.23 v1@1961.79,1820.53
  TOP LAYER w20: v1@1961.79,1820.53 2035.68,1820.53 2055,1839.84 C70.2@2055,1953.5 2088.42,1953.5 v1(2088.79,1953.13)
  SIG2#4 w5: v1(1859.82,1816.55) 1829.68,1816.55 1818.65,1827.58 1818.65,1862.62 1860.15,1904.12 1992.93,1904.12 2050.62,1846.43 2050.62,1830.72 2041.66,1821.76 ; 1860,425 1860,1127.79 2003.37,1271.16 2003.37,1337.37 2047.21,1381.21 2047.21,1588 2077.9,1618.69 2077.9,1785.53 2041.66,1821.76 ; v1(1961.79,1821.76) 2041.66,1821.76
  BOTTOM LAYER w25: v1(1859.82,1816.55) 1876.9,1799.47 1939.5,1799.47 v1(1961.79,1821.76) ; v1(2088.79,1953.13) 2088.79,1895.96 2104.25,1880.5 U26.3@2133,1880.5
  BOTTOM LAYER w50: v1(1729.67,1171.25) 1730,1170.92 R70.1@1730,1075.47
  other v1: 1835,1025 1835,1060 1835,1105 1670.26,1172.13 1785,1172 2088.93,1924.62 1772.3,1939.06 1771.86,1963.31
V3.3DX_AUDIO: "V3.3Dx_AUDIO [3.3V,0.20A].1" C69.2 R69.1 U4.1 U25.3 | length 1612.1
  TOP LAYER w6: v1(1841.81,1662.1) 1848.7,1655.21 1875.39,1655.21 1883.5,1663.32 U4.1@1883.5,1679.57
  TOP LAYER w25: C69.2@1750,1531.5 1750,1564.21 v1(1767.03,1581.24)
  SIG3#6 w5: 1550,430 1550,1178.91 1522.62,1206.29 1522.62,1409.62 1761.24,1648.24 1827.95,1648.24 v1(1841.81,1662.1)
  BOTTOM LAYER w20: R69.1@1720,1540.08 1746.87,1540.08 1767.03,1560.24 v1(1767.03,1581.24)
V3.3DX_DPWP: "V3.3Dx_DPWP [3.3V,0.50A].1" C85.2 R82.1 U5.1 U28.3 | length 2035.5
  TOP LAYER w8: v1(3247.2,1726.77) 3247.2,1710.37 3256.07,1701.5 U5.1@3279.88,1701.5
  TOP LAYER w25: v1@3179.4,1894.19 3186,1900.79 v1(3186,1935)
  TOP LAYER w30: C85.2@3126.5,1895 3127.31,1894.19 v1@3179.4,1894.19
  SIG3#6 w5: v1(3247.2,1726.77) 3256.18,1735.75 3374.3,1735.75 3444.06,1805.51 3444.06,2402.24 3661.48,2619.66 3661.48,3111.48 3785,3235
  BOTTOM LAYER w30: R82.1@3100,1894.92 3178.67,1894.92 3179.4,1894.19 3180.21,1895 v1(3185.11,1895)
V3.3DX_EDP: "V3.3Dx_EDP [3.3V,0.75A].1" C59.2 R58.1 U3.1 U21.3 | length 1377.1
  TOP LAYER w6: v1(820.65,1587.24) 821.29,1587.24 828.5,1594.45 U3.1@828.5,1609.88
  TOP LAYER w20: v1@820.65,1586.6 v1(820.65,1587.24)
  TOP LAYER w25: C59.2@700,1441.5 v1@700,1489.81
  SIG3#6 w5: 600,440 600,634.95 707.09,742.04 707.09,1415.99 732.1,1441 732.1,1498.69 v1(820.65,1587.24)
  BOTTOM LAYER w30: v1(699.85,1489.96) 720,1469.81 R58.1@720,1435.08
  other v1: 668.77,1487.89
V3.3DX_SENSORS: "V3.3Dx_SENSORS [3.3V,0.09A].1" C61.2 R61.1 U3.11 U23.3 | length 2359.4
  TOP LAYER w6: U3.11@891.5,1720.12 891.5,1735.55 906.79,1750.84 v1(906.79,1752.08)
  TOP LAYER w20: C61.2@995,1878.5 1049.57,1878.5 v1(1054.42,1873.65) 1044.33,1883.74 v1(1044.33,1914.55)
  SIG3#6 w5: v1(906.79,1752.08) 987.23,1752.08 1245.56,1493.75 1245.56,609.22 1186.58,550.24 1025.24,550.24 915,440
  BOTTOM LAYER w20: R61.1@970,1874.92 1053.15,1874.92 v1(1054.42,1873.65)
  BOTTOM LAYER w25: v1(906.79,1752.08) 970,1815.29 R61.1@970,1874.92 1014.55,1919.47 1014.55,2005.15 1044.9,2035.5 U23.3@1103,2035.5
V3.3DX_SSD: "V3.3Dx_SSD [3.3V,2.50A].1" C95.2 R94.1 U6.1 U6.11 U6.15 U31.3 | length 1702.7
  TOP LAYER w6: v1(3168.53,998.18) 3168.53,986.36 3183.39,971.5 U6.1@3204.88,971.5 ; U6.11@3315.12,908.5 3329.77,908.5 v1(3354.96,883.31) ; U6.15@3315.12,971.5 3333.74,971.5 3350.07,987.83 v1(3350.07,998.08)
  TOP LAYER w20: v1(3354.96,883.31) 3394.3,843.97 v1(3490.19,843.97) ; 3370,1028.99 C95.2@3370,1058.5
  SIG3#6 w5: 2810,430 2810,655.06 2859.05,704.11 3027.52,704.11 3074.68,751.27 3244.09,751.27 3277.25,784.43 3277.25,874.16 3257.03,894.38 3257.03,975.51 ; v1(3168.53,998.18) 3234.36,998.18 3257.03,975.51 ; v1(3350.07,998.08) 3279.6,998.08 3257.03,975.51 ; v1(3354.96,883.31) 3323.9,914.37 3323.9,953.78 3302.17,975.51 3257.03,975.51
  BOTTOM LAYER w20: U31.3@3450.5,817 3479.27,817 3490.19,827.92 v1(3490.19,843.97)
  other v1: 3458.87,843.97 3374.65,865.85 2798.62,979.98 2627.9,983.31 2627.9,1013.09 2800,1015 3168.16,1020.45 3360.74,1022.41 2627.9,1044.89 2799.56,1046.74
V3.3DX_TOUCHSCREEN: "V3.3Dx_TOUCHSCREEN [3.3V,0.20A].1" C84.2 R81.1 U5.5 U27.3 | length 1866.6
  TOP LAYER w8: v1(3248.51,1615.19) 3248.51,1629.16 3257.85,1638.5 U5.5@3279.88,1638.5
  TOP LAYER w20: C84.2@3036.5,1550 3061.5,1575 v1(3075,1575) 3115.86,1575 v1(3116.29,1575.43)
  SIG3#6 w5: v1(3248.51,1615.19) 3248.51,1682.02 3279.5,1713.01 3373.36,1713.01 3471.6,1811.25 3471.6,2388.16 3679.79,2596.35 3679.79,2959.79 3785,3065
V3.3DX_USBSDIO: "V3.3Dx_USBSDIO [3.3V,0.80A].1" C58.2 R56.1 U3.5 U20.3 | length 1492.9
  TOP LAYER w5: U3.5@891.5,1609.88 891.5,1591.29 v1@909.62,1573.17
  TOP LAYER w6: v1@909.62,1573.17 v1(909.62,1574.74)
  TOP LAYER w25: C58.2@1040,1431.5 1085.33,1431.5 v1(1089.84,1436.01)
  SIG2#4 w5: v1(909.62,1574.74) 940,1574.74 955,1559.74 955,1530 940,1515 940,901.4 1008.44,832.96 1008.44,596.41 1053.96,550.89 1124.11,550.89 1240,435
  BOTTOM LAYER w25: R56.1@1005,1435.08 R56.1@1052.52,1435.08
  other v1: 1053.25,1488.32 970.36,1488.89
V3.3DX_WIFI: "V3.3Dx_WIFI [3.3V,2.00A].1" C86.2 R84.1 U5.11 U5.15 U29.3 | length 2219.6
  TOP LAYER w6: U5.11@3390.12,1638.5 3405.55,1638.5 3420.84,1623.21 v1(3422.08,1623.21) ; U5.15@3390.12,1701.5 3412.23,1701.5 3420.66,1709.93 v1@3420.66,1722.43
  TOP LAYER w20: v1@3420.66,1731.03 3420.66,1792.17 3463.49,1835 C86.2@3493.5,1835
  SIG2#4 w5: v1(3422.08,1623.21) 3422.08,1598.04 3433.91,1586.21 3482.56,1586.21 3502.22,1605.87 3502.22,1757.96 3476.45,1783.73 ; v1(3423.75,1731.03) 3476.45,1783.73 ; 3785,2870 3608.99,2693.99 3608.99,2089.43 3476.45,1956.89 3476.45,1783.73
  BOTTOM LAYER w28: v1(3462,1562) 3465.5,1558.5 U29.3@3465.5,1497
  BOTTOM LAYER w30: v1(3423.75,1731.03) 3402.97,1710.25 3402.97,1642.32 v1(3422.08,1623.21) 3462,1583.29 v1(3462,1562)
  BOTTOM LAYER w50: v1(3774.39,808.25) 3775,807.64 R84.1@3775,689.53
  other v1: 3718.39,807.61 3838.39,810.61 3463.15,1534.47
V3.3M: "V3.3M [3.3V,0.22A].1" C68.2 R68.1 U4.5 U24.3 | length 2021
  TOP LAYER w6: 1964.62,1642.86 1964.62,1644.43
  TOP LAYER w8: U4.5@1946.5,1679.57 1946.5,1667.76 v1(1956.68,1657.58)
  TOP LAYER w25: C68.2@2090,1536.5 v1(2090,1575)
  SIG2#4 w5: v1(1956.68,1657.58) 1978.86,1635.4 1978.86,1607.86 1853,1482 1853,1281.15 1753.51,1181.66 1753.51,354.87 1807.97,300.41 2035.41,300.41 2165,430
  BOTTOM LAYER w25: R68.1@2075.42,1520.5 R68.1@2075,1520.08 2075,1560 v1(2090,1575)
  other v1: 2118.61,1574.07
V3.3S: "V3.3S [3.3V,0.03A].1" C94.2 R93.1 U6.5 U30.3 | length 1120.5
  TOP LAYER w6: v1(3179.53,890.83) 3179.53,901.21 3186.82,908.5 U6.5@3204.88,908.5
  TOP LAYER w25: C94.2@3061.5,865 3061.5,828.79 3088.37,801.92 v1(3124.76,801.92)
  SIG2#4 w5: 2500,428.45 2629.88,428.45 2838.6,637.17 2838.6,697.77 3001.96,861.13 3149.83,861.13 v1(3179.53,890.83)
  BOTTOM LAYER w20: R93.1@3076.9,795.19 R93.1@3070,802.09 3124.59,802.09 v1(3124.76,801.92)
  other v1: 3125.07,776.06
V4(1.00V): "U7_V4 (1.00V).1" C100.1 C103.1 C106.1 L6.2 R115.2 U7.2 U7.4 U7.12 U7.14 U11.14 U36.3 | length 2301.4
  TOP LAYER w8: v1(889.01,2568.17) 889.24,2568.4 893.39,2564.25 U7.4@929.88,2564.25 ; v1(889.47,2594.56) 890.66,2595.75 U7.2@929.88,2595.75 ; U7.12@1040.12,2564.25 1075.3,2564.25 v1(1077.31,2566.26) ; U7.14@1040.12,2595.75 1078.45,2595.75 v1(1082.02,2592.18)
  TOP LAYER w10: v1(1350,2727) 1366.16,2710.84 U11.14@1425.93,2710.84
  TOP LAYER w20: v1(1595,2519) R115.2@1595,2558.5
  SIG2#4 w5: 890,3325 890,3315.92 955.35,3250.57 1040.01,3250.57 1160,3130.58 1160,3027.15 1186.25,3000.9 1186.25,2766.8 1157.78,2738.33 1157.78,2553.35 1090.93,2486.5 1004.58,2486.5 986.91,2504.17 986.91,2528.47
  SIG2#4 w20: v1(1303,2584) 1311,2592 1311,2700 1338,2727 v1(1350,2727)
  SIG3#6 w20: v1(1303,2584) 1303,2379 1334,2348 1507,2348 1595,2436 v1(1595,2519)
  BOTTOM LAYER w20: v1(808.54,3090.65) 808.69,3090.5 U36.3@838,3090.5
  other v1: 808.93,3062.8
pads on no net: FID1.1 FID2.1 FID3.1 FID4.1 FID5.1 FID6.1 H1.1 H2.1 H3.1 H4.1 H5.0 H6.0 H7.0 H8.0 J1.2 J1.6 J1.8 J1.9 J1.10 J1.21 J1.22 J1.23 J1.24 U1.21 U1.22 U1.23 U1.24 U2.21 U2.22 U2.23 U2.24 U3.21 U3.22 U3.23 U3.24 U4.21 U4.22 U4.23 U4.24 U5.21 U5.22 U5.23 U5.24 U6.21 U6.22 U6.23 U6.24 U7.21 U7.22 U7.23 U7.24 U8.4 U9.F4 U10.F4 U11.4

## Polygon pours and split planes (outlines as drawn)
GND on TOP LAYER "Top Layer-No Net" (solid, pour order 190): 3675,1647 3628,1647 3595,1680 3595,1790 3580,1805 3560,1805 3550,1815 3550,1875 3555,1880 3620,1880 3630,1870 3695,1805 3695,1740 3695,1667 3675,1647
GND on TOP LAYER "Top Layer-No Net" (solid, pour order 312): 1228,2861 1338,2861 1338,2794 1310,2794 1310,2720 1334,2696 1428.88,2696 1428.88,2671.47 1430,2670.35 1430,2650 1420,2640 1162,2640 1145,2657 1145,2778
V4(1.00V) on TOP LAYER "Top Layer-No Net" (solid, pour order 197): 27 vertices, not listed, extent 751.85,2182.06 1404.75,2624.09
GND on TOP LAYER "Top Layer-No Net" (solid, pour order 187): 3560,905 3580,885 3650,885 3665,900 3665,1025 3650,1040 3575,1040 3560,1025
V3(3.3V) on TOP LAYER "Top Layer-No Net" (solid, pour order 193): 92 vertices, not listed, extent 2590.26,882.06 3670.15,1838.3
GND on TOP LAYER "Top Layer-No Net" (solid, pour order 188): 1885.8,1996.2 1860,2022 1860,2170 1884.3,2194.3 1995.2,2194.3 1995.2,2119.6 2019.3,2095.5 2063.9,2095.5 2075.6,2083.8 2075.6,1996.2
V2(3.3V) on TOP LAYER "Top Layer-No Net" (solid, pour order 189): 77 vertices, not listed, extent 784.67,1389.18 1975.8,1968
GND on TOP LAYER "Top Layer-No Net" (solid, pour order 180): 25 vertices, not listed, extent 1719,1409 2121,1539
GND on TOP LAYER "Top Layer-No Net" (solid, pour order 212): 20 vertices, not listed, extent 711.56,1891 1026.42,2019.12
GND on TOP LAYER "Top Layer-No Net" (solid, pour order 217): 790.6,1398.14 793.74,1395 1050.39,1395 1062.7,1382.69 1062.7,1316.02 1056.48,1309.8 684.1,1309.8 671.42,1322.48 671.42,1391.3 678.26,1398.14
V1(1.8V) on TOP LAYER "Top Layer-No Net" (solid, pour order 185): 71 vertices, not listed, extent 2017,2034 3282.34,2630
GND on TOP LAYER "Top Layer-No Net" (solid, pour order 206): 3305,2557 3344.93,2557 3366.95,2579.02 3400.73,2579.13 3477.59,2579.13 3477.8,2578.92 3482,2583 3482,2672 3446,2707 3299,2707 3297,2705 3297,2609 3305,2601
GND on TOP LAYER "Top Layer-No Net" (solid, pour order 204): 2540,2555 2598,2555 2612.61,2569.61 2612.61,2796.62 2598.13,2811.1 2543.85,2811.1 2531.11,2798.36 2531.31,2797.82 2531.31,2633.69 2540,2625
GND on TOP LAYER "DCDC_GND" (solid, remove dead copper, pour order 183): 19 vertices, not listed, extent 1450.6,2667.18 1682,2932
NetC99_1 on TOP LAYER "DCDC_GND" (solid, remove dead copper, pour order 192): 1565,2840 1520,2840 1514,2834 1514,2790 1508,2784 1508,2744 1510,2742 1517,2742 1520,2745 1520,2754 1520,2761 1537,2778 1559,2800 1565,2800
NetR115_1 on TOP LAYER "DCDC_GND" (solid, remove dead copper, pour order 186): 1528,2677 1569,2677 1576,2684 1576,2709 1580,2709 1615,2709 1622,2709 1625,2709 1630,2704 1630,2607 1625,2602 1624,2601 1576,2601 1528,2649
GND on TOP LAYER "Top Layer-No Net" (solid, pour order 350): 456.12,3454.94 528.25,3454.94 543.04,3440.15 543.04,3384.11 531.88,3372.95 531.62,3373.21 446.79,3373.21 439,3381 439,3437.82
GND on TOP LAYER "Top Layer-No Net" (solid, pour order 354): 3319.04,268.06 3328.23,258.87 3328.23,210.76 3317.14,199.67 3239.78,199.67 3227.99,211.46 3227.99,261.64 3234.41,268.06
GND on TOP LAYER "Top Layer-No Net" (solid, pour order 353): 3023.72,267.48 3178.71,267.48 3183.55,262.64 3189.54,256.65 3189.54,233.52 3189.54,214.12 3181.26,205.84 3178.98,203.56 3119.04,203.56 3025.61,203.56 3016.74,212.43 3015.7,213.47 3015.7,244.86 3015.7,259.65
GND on TOP LAYER "Top Layer-No Net" (solid, pour order 352): 20 vertices, not listed, extent 504.78,588.69 588.75,670.3
GND on TOP LAYER "Top Layer-No Net" (solid, pour order 351): 18 vertices, not listed, extent 302.24,593.89 487.7,676.08
GND on TOP LAYER "Top Layer-No Net" (solid, pour order 349): 18 vertices, not listed, extent 555.31,3371.6 730.82,3454.99
V1.8DX_WIFI on TOP LAYER "Top Layer-No Net" (solid, pour order 285): 3217.36,2736.19 3263.91,2736.19 3272.96,2727.14 3272.96,2669.06 3269.82,2665.92 3212.41,2665.92 3200.18,2678.15 3200.18,2719.01
V3.3A_EC on TOP LAYER "Top Layer-No Net" (solid, pour order 346): 705.26,1901.41 756.84,1901.41 762.24,1896.01 765.84,1892.41 765.84,1817.74 765.84,1807.24 756.24,1797.64 754.44,1795.84 734.65,1795.84 714.26,1795.84 703.16,1806.94 694.16,1815.94 694.16,1860.32 694.16,1890.01 705.26,1901.11
GND on TOP LAYER "Top Layer-No Net" (solid, pour order 344): 18 vertices, not listed, extent 3160.69,1190.26 3253.39,1245.22
BATT+ on TOP LAYER "Top Layer-No Net" (solid, pour order 329): 18 vertices, not listed, extent 1797.23,1505.87 1863.1,1579.89
BATT+ on TOP LAYER "Top Layer-No Net" (solid, pour order 328): 757.56,1513.5 801.74,1513.5 810.71,1504.53 813.12,1502.12 813.12,1454.5 813.12,1421.37 810.01,1418.26 809.66,1418.61 793.45,1418.61 748.25,1418.61 744.8,1422.06 743.07,1423.79 743.07,1432.41 743.07,1499.7 756.87,1513.5
GND on TOP LAYER "Top Layer-No Net" (solid, pour order 325): 663.28,2780.17 740.29,2780.17 747.91,2772.55 747.91,2721.1 730.34,2703.53 730.34,2472.06 716.26,2457.98 643.99,2457.98 621.49,2480.48 621.49,2662.49 641.88,2682.88 641.88,2758.77
BATT+ on TOP LAYER "Top Layer-No Net" (solid, pour order 327): 20 vertices, not listed, extent 755.83,2638.66 840.36,2705.67
V4(1.00V) on TOP LAYER "Top Layer-No Net" (solid, pour order 243): 848.48,2623.99 873.3,2623.99 903.52,2593.77 903.52,2567.58 888.34,2552.4 851.57,2552.4 840.59,2563.38 840.59,2616.1
V1.8DX_3G4G on TOP LAYER "Top Layer-No Net" (solid, pour order 283): 2907.54,2758.56 2918.58,2747.52 2918.58,2688.15 2911.68,2681.26 2839.56,2681.26 2836.45,2684.36 2836.8,2684.72 2836.8,2755.45 2839.9,2758.56
BATT+ on TOP LAYER "Top Layer-No Net" (solid, pour order 321): 2839.14,2659.6 2909.13,2659.6 2915.1,2653.63 2915.63,2653.1 2915.63,2622.78 2915.63,2617.86 2888.92,2591.15 2888.65,2590.88 2847.95,2590.88 2842.25,2590.88 2837.58,2595.55 2836.28,2596.85 2836.28,2625.89 2836.28,2656.48 2839.14,2659.34
V1(1.8V) on TOP LAYER "Top Layer-No Net" (solid, pour order 320): 2833.2,2515.3 2833.2,2564.75 2841.74,2573.29 2898.5,2573.29 2905.62,2566.17 2905.62,2519.67 2895.93,2509.98 2838.52,2509.98
GND on TOP LAYER "Top Layer-No Net" (solid, pour order 319): 2707.49,2753.68 2803.78,2753.68 2816.06,2741.4 2816.06,2663.9 2811.05,2658.89 2811.05,2419.61 2803.12,2411.68 2730.08,2411.68 2705.82,2435.94 2705.82,2752.21 2707.32,2753.71
GND on TOP LAYER "Top Layer-No Net" (solid, pour order 316): 2910.25,1179.82 3002.18,1179.82 3005.71,1176.29 3005.71,910.16 3019.62,896.25 3019.62,847.67 3013.04,841.09 2951.74,841.09 2892.1,900.73 2892.1,1161.67
BATT+ on TOP LAYER "Top Layer-No Net" (solid, pour order 317): 18 vertices, not listed, extent 3031.8,897.48 3087.7,992.46
BATT+ on TOP LAYER "Top Layer-No Net" (solid, pour order 315): 18 vertices, not listed, extent 3103.01,1783.88 3184.06,1855
GND on TOP LAYER "Top Layer-No Net" (solid, pour order 207): 3006.4,1596.57 3050.5,1596.57 3075.81,1621.88 3075.81,1794.26 3087.4,1805.85 3087.4,1912.83 3081.05,1919.18 2970.98,1919.18 2951.98,1900.18 2951.98,1532.14 2955.46,1528.66 2990.04,1528.66 2992.84,1531.46 2992.84,1583.01
V1.8DX_AUDIO on TOP LAYER "Top Layer-No Net" (solid, pour order 279): 18 vertices, not listed, extent 2428.32,2734.79 2508.74,2803.52
MODPHY on TOP LAYER "Top Layer-No Net" (solid, pour order 264): 769.98,2745.7 769.98,2786.81 785.98,2802.81 850.29,2802.81 855,2798.1 855,2731.9 844.95,2721.85 773.44,2721.85 769.67,2725.62 769.67,2749.15
MODPHY on TOP LAYER "Top Layer-No Net" (solid, pour order 262): 1027.52,2475.73 1109.65,2475.73 1128.76,2456.62 1130.48,2454.9 1130.48,2421.26 1130.48,2416.41 1121.35,2407.28 1121.06,2406.99 1085.41,2406.99 1034.08,2406.99 1024.95,2416.12 1022.67,2418.4 1022.67,2448.92 1022.67,2470.6 1028.09,2476.02
GND on TOP LAYER "Top Layer-No Net" (solid, pour order 261): 980.72,2854.14 980.72,2889.19 988.94,2897.41 989.13,2897.6 1041.8,2897.6 1042.58,2897.6 1045.32,2894.86 1045.91,2894.27 1045.91,2877.43 1045.91,2849.05 1042.78,2845.92 1042.39,2845.53 1016.94,2845.53 989.33,2845.53 980.72,2854.14
GND on TOP LAYER "Top Layer-No Net" (solid, pour order 259): 2251.77,2834.35 2312.74,2834.35 2317.69,2829.4 2320.82,2826.27 2320.82,2804.91 2320.82,2790.31 2313.53,2783.02 2312.23,2781.72 2291.64,2781.72 2255.67,2781.72 2248.64,2788.75 2247.08,2790.31 2247.08,2817.94 2247.08,2829.66 2251.77,2834.35
GND on TOP LAYER "Top Layer-No Net" (solid, pour order 255): 3239.23,1245.22 3294.9,1245.22 3301.06,1239.06 3302.72,1237.4 3302.72,1218.93 3302.72,1194.53 3300.59,1192.4 3298.45,1190.26 3271.69,1190.26 3240.66,1190.26 3234.97,1195.95 3234.73,1196.19 3234.73,1218.69 3234.73,1240.24 3239.71,1245.22
GND on TOP LAYER "Top Layer-No Net" (solid, pour order 253): 18 vertices, not listed, extent 1639.36,1705.77 1684.97,1774.1
GND on TOP LAYER "Top Layer-No Net" (solid, pour order 252): 534.4,1738.46 588.43,1738.46 594.11,1732.78 598.6,1728.29 598.6,1719.51 598.6,1688.48 595.05,1684.93 594.81,1684.69 560.7,1684.69 541.52,1684.69 528.49,1697.72 528.49,1732.31 534.64,1738.46
GND on TOP LAYER "Top Layer-No Net" (solid, pour order 250): 356.71,2607.77 356.71,2696.91 365.03,2705.23 367.11,2707.31 394.51,2707.31 407.35,2707.31 413.94,2700.72 417.41,2697.25 417.41,2667.08 417.41,2612.97 407.35,2602.91 406.66,2602.22 377.87,2602.22 361.56,2602.22 356.36,2607.42
GND on TOP LAYER "Top Layer-No Net" (solid, pour order 249): 266.77,2337.48 266.77,2425.93 276.48,2435.64 277.18,2436.34 307,2436.34 321.22,2436.34 330.59,2426.97 330.59,2365.58 330.59,2340.95 322.96,2333.32 285.16,2333.32 271.28,2333.32 266.77,2337.83
V3(3.3V) on TOP LAYER "Top Layer-No Net" (solid, pour order 232): 3241.01,1642.76 3202.18,1642.76 3190.33,1654.61 3190.33,1689.08 3199.58,1698.33 3239.78,1698.33 3255.8,1682.31 3255.8,1657.55
V3(3.3V) on TOP LAYER "Top Layer-No Net" (solid, pour order 234): 3395.27,910.28 3347.25,910.28 3338.78,918.75 3338.78,954.9 3349.73,965.85 3389.89,965.85 3400.87,954.87 3400.87,915.88
V3(3.3V) on TOP LAYER "Top Layer-No Net" (solid, pour order 235): 3171.8,915.23 3123.78,915.23 3111.93,927.08 3111.93,961.55 3121.18,970.8 3166.42,970.8 3181.07,956.15 3181.07,924.5
GND on TOP LAYER "Top Layer-No Net" (solid, pour order 245): 1045,2385 1120,2385 1130,2375 1130,2360 1130,2320 1125,2315 1120,2310 1085,2310 1050,2310 1040,2320 1040,2350 1040,2380 1045,2385
V2(3.3V) on TOP LAYER "Top Layer-No Net" (solid, pour order 238): 1888.26,1823.03 1888.26,1871.05 1897.96,1880.75 1900.11,1882.9 1922.51,1882.9 1934.58,1882.9 1941.04,1876.44 1943.83,1873.65 1943.83,1838.97 1943.83,1828.41 1936.08,1820.66 1932.85,1817.43 1905.92,1817.43 1893.86,1817.43 1888.48,1822.81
